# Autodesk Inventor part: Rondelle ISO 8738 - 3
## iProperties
Created: 2011-01
Part Number: Rondelle ISO 8738 - 3
Document SubType Name: Modeling
Designer: eric
Density: 1 g/cm^3
Mass: 0.0169646 g
Surface Area: 0.65031 cm^2
Volume: 0.0169646 cm^3
Author: eric
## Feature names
1. Base1
